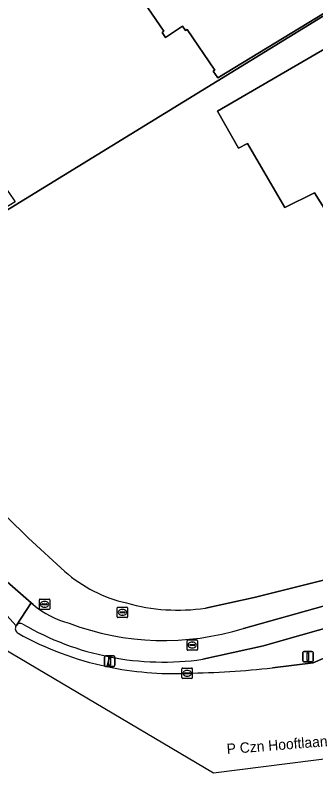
# Model space of a CAD drawing. Extents: x 161087 to 161926, y 382572 to 383873.
# Drawn here: x 161709.7 to 161738.7, y 382571.9 to 382644.9 of the extents above; entities that cross this region are included whole.
import ezdxf

# ---------------------------------------------------------------- set-up
doc = ezdxf.new("R2010")
doc.units = 0
for name, color, linetype in [('IMGEO_Brandkraan', 7, 'Continuous'), ('IMGEO_Erf', 7, 'Continuous'), ('IMGEO_Fietspad_open', 7, 'Continuous'), ('IMGEO_Kolk', 7, 'Continuous'), ('IMGEO_Lichtmast', 7, 'Continuous'), ('IMGEO_Openbare_ruimte_label', 7, 'Continuous'), ('IMGEO_Pand', 7, 'Continuous'), ('IMGEO_Rijbaan_lokaal_gesloten', 7, 'Continuous'), ('IMGEO_Rioolput', 7, 'Continuous'), ('IMGEO_Verkeerseiland_groen', 7, 'Continuous'), ('IMGEO_Verkeerseiland_open', 7, 'Continuous'), ('IMGEO_Voetpad_open', 7, 'Continuous')]:
    doc.layers.add(name, color=color, linetype=linetype)

msp = doc.modelspace()

# ---------------------------------------------------------------- linework, layer by layer
at = {"layer": 'IMGEO_Brandkraan'}
for p, q in [((161719.55, 382586.907), (161719.55, 382587.759)), ((161719.625, 382587.833), (161720.477, 382587.833)), ((161720.551, 382587.759), (161720.551, 382586.907)), ((161719.809, 382587.327), (161719.809, 382587.339)), ((161720.247, 382587.29), (161719.849, 382587.29)), ((161719.852, 382587.376), (161720.25, 382587.376)), ((161720.061, 382587.053), (161720.036, 382587.053)), ((161720.038, 382587.613), (161720.063, 382587.613)), ((161720.293, 382587.339), (161720.293, 382587.327)), ((161720.477, 382586.833), (161719.625, 382586.833))]:
    msp.add_line(p, q, dxfattribs=at)
for points in [[(161719.55, 382586.907), (161719.55, 382587.759)], [(161719.625, 382587.833), (161720.477, 382587.833)], [(161720.551, 382587.759), (161720.551, 382586.907)], [(161720.477, 382586.833), (161719.625, 382586.833)]]:
    msp.add_lwpolyline(points, dxfattribs=at)
for centre, radius, start, end in [((161719.627, 382587.757), 0.0765, 91.55205, 178.44795), ((161719.627, 382587.757), 0.0765, 91.55205, 178.44795), ((161720.475, 382587.757), 0.0765, 1.55205, 88.44795), ((161720.475, 382587.757), 0.0765, 1.55205, 88.44795), ((161719.849, 382587.336), 0.0403, 85.87752, 175.75265), ((161719.846, 382587.326), 0.0366, 178.93798, 274.71019), ((161720.25, 382587.333), 0.043, 264.86636, 352.45326), ((161720.254, 382587.338), 0.0386, 1.73085, 96.63898), ((161719.627, 382586.909), 0.0765, 181.55205, 268.44795), ((161719.627, 382586.909), 0.0765, 181.55205, 268.44795), ((161720.475, 382586.909), 0.0765, 271.55205, 358.44795), ((161720.475, 382586.909), 0.0765, 271.55205, 358.44795)]:
    msp.add_arc(centre, radius, start, end, dxfattribs=at)
for centre, major_axis, ratio, start_param, end_param in [((161720.037, 382587.333), (-0.387, 0.002), 0.722429, 4.712389, 7.853982), ((161720.062, 382587.333), (-0.39, 0.002), 0.717154, 1.570796, 4.712389)]:
    msp.add_ellipse(centre, major_axis=major_axis, ratio=ratio, start_param=start_param, end_param=end_param, dxfattribs=at)
at = {"layer": 'IMGEO_Erf'}
for points in [[(161715.388, 382659.714), (161715.213, 382659.599), (161715.065, 382659.813), (161715.235, 382659.927), (161712.849, 382663.468), (161711.028, 382662.242), (161709.203, 382664.95), (161691.894, 382653.285), (161705.616, 382632.96), (161708.777, 382628.279), (161708.895, 382628.104), (161709.59, 382627.074), (161709.708, 382626.9), (161704.022, 382623.425), (161704.187, 382623.185), (161742.576, 382646.789), (161760.971, 382658.101), (161760.61, 382659.053), (161759.351, 382662.367), (161759.169, 382662.845), (161745.752, 382698.169)], [(161779.952, 382608.946), (161767.176, 382642.388), (161760.971, 382658.101), (161742.576, 382646.789), (161704.187, 382623.185), (161704.022, 382623.425), (161695.384, 382618.145), (161695.27, 382618.322), (161690.885, 382615.891), (161702.391, 382602.921), (161711.019, 382594.472), (161714.507, 382591.277)], [(161741.875, 382646.56), (161729.232, 382638.832), (161728.792, 382639.477), (161728.957, 382639.589), (161726.285, 382643.509), (161726.12, 382643.396), (161725.829, 382643.823), (161724.197, 382642.728), (161723.867, 382643.217), (161724.029, 382643.326), (161721.371, 382647.263)], [(161728.057, 382587.75), (161732.732, 382588.753), (161750.068, 382593.111), (161776.833, 382603.073)]]:
    msp.add_lwpolyline(points, dxfattribs=at)
msp.add_lwpolyline([(161741.604, 382622.95), (161740.588, 382624.551), (161738.551, 382627.76), (161735.712, 382626.357), (161732.093, 382632.523), (161731.239, 382632.055), (161729.226, 382635.638), (161740.719, 382642.317), (161742.584, 382639.378), (161743.349, 382639.864), (161750.5, 382628.596)], close=True, dxfattribs=at)
for centre, radius, start, end in [((161723.455, 382601.464), 13.559, 228.70703, 257.17126), ((161725.395, 382605.638), 18.085, 254.11078, 278.4639)]:
    msp.add_arc(centre, radius, start, end, dxfattribs=at)
at = {"layer": 'IMGEO_Fietspad_open'}
for points in [[(161776.981, 382598.483), (161731.713, 382585.795)], [(161727.79, 382582.818), (161733.632, 382584.112), (161735.548, 382584.657), (161745.758, 382587.539), (161767.27, 382593.561), (161777.834, 382596.519), (161780.697, 382597.213), (161780.8, 382597.237), (161780.904, 382597.262)], [(161711.463, 382588.091), (161711.27, 382588.243), (161709.816, 382586.053)]]:
    msp.add_lwpolyline(points, dxfattribs=at)
for centre, radius, start, end in [((161717.045, 382594.581), 8.561, 229.30098, 255.72209), ((161710.231, 382585.771), 0.502, 62.22181, 145.80913), ((161724.035, 382610.403), 25.778, 249.32601, 287.3285), ((161723.957, 382609.217), 26.667, 239.60564, 258.8428), ((161723.985, 382609.28), 26.734, 258.81058, 278.18292)]:
    msp.add_arc(centre, radius, start, end, dxfattribs=at)
at = {"layer": 'IMGEO_Kolk'}
for p, q in [((161725.788, 382581.045), (161725.788, 382581.897)), ((161725.863, 382581.971), (161726.715, 382581.971)), ((161726.789, 382581.897), (161726.789, 382581.045)), ((161726.047, 382581.465), (161726.047, 382581.477)), ((161726.485, 382581.428), (161726.087, 382581.428)), ((161726.09, 382581.514), (161726.488, 382581.514)), ((161726.299, 382581.191), (161726.274, 382581.191)), ((161726.276, 382581.751), (161726.301, 382581.751)), ((161726.531, 382581.477), (161726.531, 382581.465)), ((161726.715, 382580.971), (161725.863, 382580.971))]:
    msp.add_line(p, q, dxfattribs=at)
for points in [[(161725.788, 382581.045), (161725.788, 382581.897)], [(161725.863, 382581.971), (161726.715, 382581.971)], [(161726.789, 382581.897), (161726.789, 382581.045)], [(161726.715, 382580.971), (161725.863, 382580.971)]]:
    msp.add_lwpolyline(points, dxfattribs=at)
for centre, radius, start, end in [((161725.865, 382581.895), 0.0765, 91.55205, 178.44795), ((161725.865, 382581.895), 0.0765, 91.55205, 178.44795), ((161726.713, 382581.895), 0.0765, 1.55205, 88.44795), ((161726.713, 382581.895), 0.0765, 1.55205, 88.44795), ((161726.087, 382581.474), 0.0403, 85.87752, 175.75265), ((161726.084, 382581.464), 0.0366, 178.93798, 274.71019), ((161726.488, 382581.471), 0.043, 264.86636, 352.45326), ((161726.492, 382581.476), 0.0386, 1.73085, 96.63898), ((161725.865, 382581.047), 0.0765, 181.55205, 268.44795), ((161725.865, 382581.047), 0.0765, 181.55205, 268.44795), ((161726.713, 382581.047), 0.0765, 271.55205, 358.44795), ((161726.713, 382581.047), 0.0765, 271.55205, 358.44795)]:
    msp.add_arc(centre, radius, start, end, dxfattribs=at)
for centre, major_axis, ratio, start_param, end_param in [((161726.275, 382581.471), (-0.387, 0.002), 0.722429, 4.712389, 7.853982), ((161726.3, 382581.471), (-0.39, 0.002), 0.717154, 1.570796, 4.712389)]:
    msp.add_ellipse(centre, major_axis=major_axis, ratio=ratio, start_param=start_param, end_param=end_param, dxfattribs=at)
at = {"layer": 'IMGEO_Lichtmast'}
for p, q in [((161737.425, 382582.66), (161737.425, 382583.46)), ((161737.425, 382583.46), (161737.425, 382582.66)), ((161737.525, 382583.56), (161738.315, 382583.56)), ((161738.315, 382583.56), (161737.525, 382583.56)), ((161738.415, 382583.46), (161738.415, 382582.66)), ((161738.415, 382582.66), (161738.415, 382583.46)), ((161718.319, 382582.236), (161718.319, 382583.036)), ((161718.319, 382583.036), (161718.319, 382582.236)), ((161718.419, 382583.136), (161719.209, 382583.136)), ((161719.209, 382583.136), (161718.419, 382583.136)), ((161719.309, 382583.036), (161719.309, 382582.236)), ((161719.309, 382582.236), (161719.309, 382583.036)), ((161719.209, 382582.136), (161718.419, 382582.136)), ((161718.419, 382582.136), (161719.209, 382582.136)), ((161738.315, 382582.56), (161737.525, 382582.56)), ((161737.525, 382582.56), (161738.315, 382582.56))]:
    msp.add_line(p, q, dxfattribs=at)
for points in [[(161737.845, 382583.435), (161737.995, 382583.435), (161737.995, 382582.685), (161737.845, 382582.685), (161737.845, 382583.435)], [(161718.739, 382583.011), (161718.889, 382583.011), (161718.889, 382582.261), (161718.739, 382582.261), (161718.739, 382583.011)]]:
    msp.add_lwpolyline(points, dxfattribs=at)
for centre, start, end in [((161737.525, 382583.46), 90, 180), ((161737.525, 382583.46), 90, 180), ((161738.315, 382583.46), 0, 90), ((161738.315, 382583.46), 360, 90), ((161718.419, 382583.036), 90, 180), ((161718.419, 382583.036), 90, 180), ((161719.209, 382583.036), 0, 90), ((161719.209, 382583.036), 360, 90), ((161737.525, 382582.66), 180, 270), ((161737.525, 382582.66), 180, 270), ((161738.315, 382582.66), 270, 0), ((161738.315, 382582.66), 270, 0), ((161718.419, 382582.236), 180, 270), ((161718.419, 382582.236), 180, 270), ((161719.209, 382582.236), 270, 0), ((161719.209, 382582.236), 270, 0)]:
    msp.add_arc(centre, 0.1, start, end, dxfattribs=at)
at = {"layer": 'IMGEO_Pand'}
msp.add_lwpolyline([(161721.371, 382647.263), (161724.029, 382643.326), (161723.867, 382643.217), (161724.197, 382642.728), (161725.829, 382643.823), (161726.12, 382643.396), (161726.285, 382643.509), (161728.957, 382639.589), (161728.792, 382639.477), (161729.232, 382638.832), (161741.875, 382646.56)], dxfattribs=at)
msp.add_lwpolyline([(161743.349, 382639.864), (161742.584, 382639.378), (161740.719, 382642.317), (161729.226, 382635.638), (161731.239, 382632.055), (161732.093, 382632.523), (161735.712, 382626.357), (161738.551, 382627.76), (161740.588, 382624.551), (161741.604, 382622.95), (161750.5, 382628.596)], close=True, dxfattribs=at)
at = {"layer": 'IMGEO_Rijbaan_lokaal_gesloten'}
for points in [[(161563.602, 382736.77), (161592.087, 382705.487), (161622.627, 382671.947), (161661.586, 382630.771), (161701.238, 382588.176), (161728.827, 382571.874), (161779.525, 382578.285), (161779.123, 382582.55), (161766.2, 382581.371), (161761.033, 382580.909)], [(161709.816, 382586.053), (161680.185, 382618.886), (161643.825, 382659.427), (161627.635, 382677.479), (161586.909, 382721.287), (161583.729, 382724.844), (161582.233, 382726.427)], [(161643.825, 382659.427), (161680.185, 382618.886), (161709.816, 382586.053), (161711.27, 382588.243), (161708.423, 382590.72), (161708.255, 382590.889), (161707.678, 382591.51), (161706.14, 382593.165), (161704.614, 382594.867), (161699.125, 382600.989), (161695.676, 382604.795), (161691.858, 382608.899), (161691.059, 382609.76), (161687.909, 382613.153), (161687.765, 382613.317), (161684.88, 382616.608), (161683.888, 382617.699), (161681.202, 382620.653), (161676.251, 382625.901), (161661.238, 382643.793), (161658.863, 382646.624), (161658.558, 382647.024), (161645.804, 382661.238)], [(161749.988, 382584.173), (161739.389, 382582.883), (161738.423, 382582.476), (161734.508, 382581.982)]]:
    msp.add_lwpolyline(points, dxfattribs=at)
for centre, radius, start, end in [((161710.23, 382585.772), 0.5, 145.87511, 242.3463), ((161724.986, 382612.264), 30.824, 240.90697, 257.9868), ((161724.975, 382612.256), 30.814, 258.00295, 272.44397), ((161724.14, 382682.188), 100.741, 271.22218, 275.90705)]:
    msp.add_arc(centre, radius, start, end, dxfattribs=at)
at = {"layer": 'IMGEO_Rioolput'}
for p, q in [((161712.055, 382587.69), (161712.055, 382588.542)), ((161712.13, 382588.616), (161712.982, 382588.616)), ((161713.056, 382588.542), (161713.056, 382587.69)), ((161712.314, 382588.11), (161712.314, 382588.122)), ((161712.752, 382588.073), (161712.354, 382588.073)), ((161712.357, 382588.159), (161712.755, 382588.159)), ((161712.566, 382587.836), (161712.541, 382587.836)), ((161712.543, 382588.396), (161712.568, 382588.396)), ((161712.798, 382588.122), (161712.798, 382588.11)), ((161712.982, 382587.616), (161712.13, 382587.616)), ((161726.283, 382583.757), (161726.283, 382584.609)), ((161726.358, 382584.683), (161727.21, 382584.683)), ((161726.542, 382584.177), (161726.542, 382584.189)), ((161726.98, 382584.14), (161726.582, 382584.14)), ((161726.585, 382584.226), (161726.983, 382584.226)), ((161726.771, 382584.463), (161726.796, 382584.463)), ((161727.026, 382584.189), (161727.026, 382584.177)), ((161727.284, 382584.609), (161727.284, 382583.757)), ((161727.21, 382583.683), (161726.358, 382583.683)), ((161726.794, 382583.903), (161726.769, 382583.903))]:
    msp.add_line(p, q, dxfattribs=at)
for points in [[(161712.055, 382587.69), (161712.055, 382588.542)], [(161712.13, 382588.616), (161712.982, 382588.616)], [(161713.056, 382588.542), (161713.056, 382587.69)], [(161712.982, 382587.616), (161712.13, 382587.616)], [(161726.283, 382583.757), (161726.283, 382584.609)], [(161726.358, 382584.683), (161727.21, 382584.683)], [(161727.284, 382584.609), (161727.284, 382583.757)], [(161727.21, 382583.683), (161726.358, 382583.683)]]:
    msp.add_lwpolyline(points, dxfattribs=at)
for centre, radius, start, end in [((161712.132, 382588.54), 0.0765, 91.55205, 178.44795), ((161712.132, 382588.54), 0.0765, 91.55205, 178.44795), ((161712.98, 382588.54), 0.0765, 1.55205, 88.44795), ((161712.98, 382588.54), 0.0765, 1.55205, 88.44795), ((161712.132, 382587.692), 0.0765, 181.55205, 268.44795), ((161712.132, 382587.692), 0.0765, 181.55205, 268.44795), ((161712.354, 382588.119), 0.0403, 85.87752, 175.75265), ((161712.351, 382588.109), 0.0366, 178.93798, 274.71019), ((161712.755, 382588.116), 0.043, 264.86636, 352.45326), ((161712.759, 382588.121), 0.0386, 1.73085, 96.63898), ((161712.98, 382587.692), 0.0765, 271.55205, 358.44795), ((161712.98, 382587.692), 0.0765, 271.55205, 358.44795), ((161726.36, 382584.607), 0.0765, 91.55205, 178.44795), ((161726.36, 382584.607), 0.0765, 91.55205, 178.44795), ((161726.582, 382584.186), 0.0403, 85.87752, 175.75265), ((161726.579, 382584.176), 0.0366, 178.93798, 274.71019), ((161726.983, 382584.183), 0.043, 264.86636, 352.45326), ((161726.987, 382584.188), 0.0386, 1.73085, 96.63898), ((161727.208, 382584.607), 0.0765, 1.55205, 88.44795), ((161727.208, 382584.607), 0.0765, 1.55205, 88.44795), ((161726.36, 382583.759), 0.0765, 181.55205, 268.44795), ((161726.36, 382583.759), 0.0765, 181.55205, 268.44795), ((161727.208, 382583.759), 0.0765, 271.55205, 358.44795), ((161727.208, 382583.759), 0.0765, 271.55205, 358.44795)]:
    msp.add_arc(centre, radius, start, end, dxfattribs=at)
for centre, major_axis, ratio, start_param, end_param in [((161712.542, 382588.116), (-0.387, 0.002), 0.722429, 4.712389, 7.853982), ((161712.567, 382588.116), (-0.39, 0.002), 0.717154, 1.570796, 4.712389), ((161726.77, 382584.183), (-0.387, 0.002), 0.722429, 4.712389, 7.853982), ((161726.795, 382584.183), (-0.39, 0.002), 0.717154, 1.570796, 4.712389)]:
    msp.add_ellipse(centre, major_axis=major_axis, ratio=ratio, start_param=start_param, end_param=end_param, dxfattribs=at)
at = {"layer": 'IMGEO_Verkeerseiland_groen'}
for points in [[(161746.238, 382585.697), (161745.758, 382587.539), (161735.548, 382584.657), (161733.632, 382584.112), (161727.79, 382582.818)], [(161734.508, 382581.982), (161738.423, 382582.476), (161739.389, 382582.883), (161746.238, 382585.697)], [(161718.797, 382583.054), (161718.57, 382582.115)]]:
    msp.add_lwpolyline(points, dxfattribs=at)
for centre, radius, start, end in [((161723.985, 382609.28), 26.734, 258.81058, 278.18292), ((161724.975, 382612.256), 30.814, 258.00295, 272.44397), ((161724.14, 382682.188), 100.741, 271.22218, 275.90705)]:
    msp.add_arc(centre, radius, start, end, dxfattribs=at)
at = {"layer": 'IMGEO_Verkeerseiland_open'}
msp.add_lwpolyline([(161718.57, 382582.115), (161718.797, 382583.054)], dxfattribs=at)
for centre, radius, start, end in [((161710.231, 382585.771), 0.502, 62.22181, 145.80913), ((161710.23, 382585.772), 0.5, 145.87511, 242.3463), ((161723.957, 382609.217), 26.667, 239.60564, 258.8428), ((161724.986, 382612.264), 30.824, 240.90697, 257.9868)]:
    msp.add_arc(centre, radius, start, end, dxfattribs=at)
at = {"layer": 'IMGEO_Voetpad_open'}
for points in [[(161658.558, 382647.024), (161658.863, 382646.624), (161661.238, 382643.793), (161676.251, 382625.901), (161681.202, 382620.653), (161683.888, 382617.699), (161684.741, 382618.476), (161691.942, 382610.568), (161691.059, 382609.76), (161691.858, 382608.899), (161695.676, 382604.795), (161699.125, 382600.989), (161704.614, 382594.867), (161704.983, 382595.204), (161708.047, 382591.847), (161707.678, 382591.51), (161708.255, 382590.889), (161708.423, 382590.72), (161711.27, 382588.243), (161711.463, 382588.091)], [(161714.507, 382591.277), (161711.019, 382594.472), (161702.391, 382602.921), (161690.885, 382615.891), (161683.298, 382624.442)], [(161776.833, 382603.073), (161750.068, 382593.111), (161732.732, 382588.753), (161728.057, 382587.75)], [(161731.713, 382585.795), (161776.981, 382598.483)]]:
    msp.add_lwpolyline(points, dxfattribs=at)
for centre, radius, start, end in [((161723.455, 382601.464), 13.559, 228.70703, 257.17126), ((161717.045, 382594.581), 8.561, 229.30098, 255.72209), ((161725.395, 382605.638), 18.085, 254.11078, 278.4639), ((161724.035, 382610.403), 25.778, 249.32601, 287.3285)]:
    msp.add_arc(centre, radius, start, end, dxfattribs=at)

# ---------------------------------------------------------------- texts
at = {"layer": 'IMGEO_Openbare_ruimte_label'}
msp.add_text('P Czn Hooftlaan', height=1, rotation=4.58763, dxfattribs=at).set_placement((161730.14, 382573.672))

doc.saveas('drawing.dxf')
